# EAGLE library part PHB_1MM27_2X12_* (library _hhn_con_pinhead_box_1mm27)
Pin Header Box-Type, 1.27mm/0.5"/50mil Pitch, 2x12 Circuits Note: see library description for an important note about THT-version
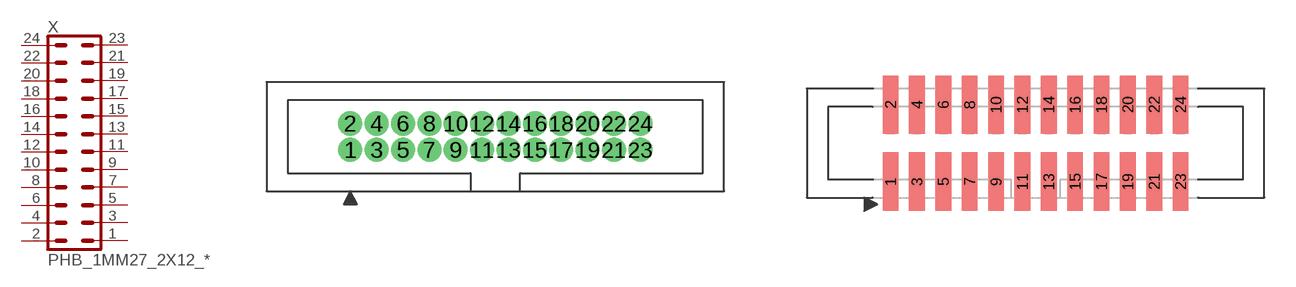
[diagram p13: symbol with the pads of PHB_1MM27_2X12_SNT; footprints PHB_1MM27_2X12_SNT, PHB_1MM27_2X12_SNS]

Designator prefix X

## PHB_1MM27_2X12_SNT  [PHB_1MM27_2X12_SNT]
1  1  pas
2  2  pas
3  3  pas
4  4  pas
5  5  pas
6  6  pas
7  7  pas
8  8  pas
9  9  pas
10  10  pas
11  11  pas
12  12  pas
13  13  pas
14  14  pas
15  15  pas
16  16  pas
17  17  pas
18  18  pas
19  19  pas
20  20  pas
21  21  pas
22  22  pas
23  23  pas
24  24  pas

## PHB_1MM27_2X12_SNS  [PHB_1MM27_2X12_SNS]
Pads as for PHB_1MM27_2X12_SNT

## Footprint PHB_1MM27_2X12_SNT (pad centres in mm)
Pin Header Box-Type, 1.27mm Pitch, 2x12 circuits, Straight, No Locking, THT Important Note: Diameter in this lbr is set to a specific value (NOT 'auto' = 0), this is ignored by actual eagle versions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
drill 0.65 pad 1 round: 1 -6.985,-0.635; 2 -6.985,0.635; 3 -5.715,-0.635; 4 -5.715,0.635; 5 -4.445,-0.635; 6 -4.445,0.635; 7 -3.175,-0.635; 8 -3.175,0.635; 9 -1.905,-0.635; 10 -1.905,0.635; 11 -0.635,-0.635; 12 -0.635,0.635; 13 0.635,-0.635; 14 0.635,0.635; 15 1.905,-0.635; 16 1.905,0.635; 17 3.175,-0.635; 18 3.175,0.635; 19 4.445,-0.635; 20 4.445,0.635; 21 5.715,-0.635; 22 5.715,0.635; 23 6.985,-0.635; 24 6.985,0.635

## Footprint PHB_1MM27_2X12_SNS (pad centres in mm)
Pin Header Box-Type, 1.27mm Pitch, 2x12 circuits, Straight, No Locking, SMT
smd 0.76 x 2.8: 1 -6.985,-1.85; 2 -6.985,1.85; 3 -5.715,-1.85; 4 -5.715,1.85; 5 -4.445,-1.85; 6 -4.445,1.85; 7 -3.175,-1.85; 8 -3.175,1.85; 9 -1.905,-1.85; 10 -1.905,1.85; 11 -0.635,-1.85; 12 -0.635,1.85; 13 0.635,-1.85; 14 0.635,1.85; 15 1.905,-1.85; 16 1.905,1.85; 17 3.175,-1.85; 18 3.175,1.85; 19 4.445,-1.85; 20 4.445,1.85; 21 5.715,-1.85; 22 5.715,1.85; 23 6.985,-1.85; 24 6.985,1.85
